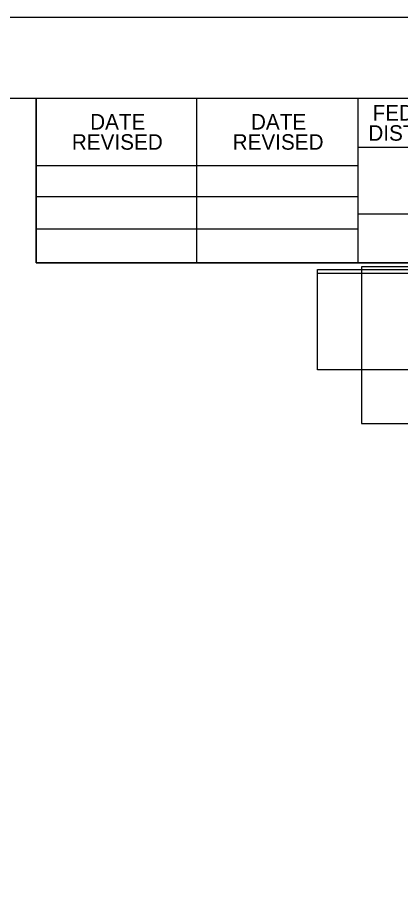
# Model space of a CAD drawing. Extents: x -0.29 to 1.42, y 0 to 0.92.
# Drawn here: x 1.1249 to 1.2237, y 0.689 to 0.9167 of the extents above; entities that cross this region are included whole.
import ezdxf

# ---------------------------------------------------------------- set-up
doc = ezdxf.new("R2010")
doc.units = 0
for name, color, linetype in [('DSN_DRFT_Guideline-No-Plot', 7, 'Continuous'), ('SHET_Border-Lines', 7, 'Continuous'), ('SHET_Border-Text', 7, 'Continuous'), ('SHET_Stamp-Prelim', 7, 'Continuous'), ('STAMP_PE DIG SIG', 7, 'Continuous'), ('STAMP_PE_BACKGROUND', 7, 'Continuous')]:
    doc.layers.add(name, color=color, linetype=linetype)

msp = doc.modelspace()

# ---------------------------------------------------------------- linework, layer by layer
at = {"layer": 'DSN_DRFT_Guideline-No-Plot'}
msp.add_lwpolyline([(0, 0), (1.41667, 0), (1.41667, 0.91667), (0, 0.91667)], close=True, dxfattribs=at)
at = {"layer": 'SHET_Border-Lines'}
for p, q in [((1.12962, 0.85338), (1.12962, 0.89583)), ((1.17114, 0.85338), (1.17114, 0.89583)), ((1.21266, 0.89583), (1.21266, 0.85338)), ((1.39583, 0.8832), (1.21266, 0.8832)), ((1.12962, 0.87856), (1.21266, 0.87856)), ((1.12962, 0.87057), (1.21266, 0.87057)), ((1.39583, 0.86601), (1.21266, 0.86601)), ((1.12962, 0.86223), (1.21266, 0.86223)), ((1.39583, 0.85338), (1.12962, 0.85338))]:
    msp.add_line(p, q, dxfattribs=at)
for points in [[(0.02083, 0.02083), (1.39583, 0.02083), (1.39583, 0.89583), (0.02083, 0.89583)], [(1.12962, 0.85338), (1.39583, 0.85338), (1.39583, 0.89583), (1.12962, 0.89583)]]:
    msp.add_lwpolyline(points, close=True, dxfattribs=at)
at = {"layer": 'SHET_Stamp-Prelim'}
msp.add_lwpolyline([(1.21366, 0.81193), (1.39483, 0.81193), (1.39483, 0.85238), (1.21366, 0.85238)], close=True, dxfattribs=at)
at = {"layer": 'STAMP_PE DIG SIG'}
msp.add_lwpolyline([(1.20225, 0.85078), (1.30225, 0.85078), (1.30225, 0.82578), (1.20225, 0.82578)], close=True, dxfattribs=at)
msp.add_lwpolyline([(1.20225, 0.85078), (1.30225, 0.85078), (1.30225, 0.82578), (1.20225, 0.82578)], close=True, dxfattribs=at)
at = {"layer": 'STAMP_PE_BACKGROUND'}
msp.add_lwpolyline([(1.20225, 0.85171), (1.30225, 0.85171), (1.30225, 0.82578), (1.20225, 0.82578)], close=True, dxfattribs=at)
msp.add_lwpolyline([(1.20225, 0.85171), (1.30225, 0.85171), (1.30225, 0.82578), (1.20225, 0.82578)], close=True, dxfattribs=at)

# ---------------------------------------------------------------- texts
at = {"layer": 'SHET_Border-Text'}
for s, p in [('FED.RD.', (1.21651, 0.89012)), ('DATE', (1.14358, 0.8878)), ('DATE', (1.1851, 0.8878)), ('DIST.NO.', (1.21541, 0.88492)), ('REVISED', (1.13885, 0.8826)), ('REVISED', (1.18037, 0.8826))]:
    msp.add_text(s, height=0.004, dxfattribs=at).set_placement(p)

doc.saveas('drawing.dxf')
